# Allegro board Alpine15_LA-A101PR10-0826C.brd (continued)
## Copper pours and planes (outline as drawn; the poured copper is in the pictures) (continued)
U2_LGATE2 on IN1 (solid shape): 57.02,33.47 57.02,31.69 56.9,31.57 56.26,31.57 56.2,31.63 56.2,32.58 56.07,32.71 56.07,33.54 56.13,33.6 56.9,33.6
U2_LGATE2 on IN3 (solid shape): 53.02,40.72 53.02,39.5 52.79,39.28 46.9,39.28 46.67,39.5 46.67,40.6 46.95,40.88 52.87,40.88
U2_PHASE1 on BOTTOM (solid shape): 60.39,34 60.39,32.93 59.07,31.61 58.59,31.61 58.51,31.68 58.51,32.55 59.3,33.34 59.3,34.05 59.33,34.07 60.32,34.07
U2_PHASE1 on BOTTOM (solid shape): 71.41,50.55 74.61,50.55 74.86,50.3 74.86,46.36 75.05,46.17 76.45,46.17 76.64,45.98 76.64,44.97 76.52,44.84 74.74,44.84 74.36,44.46 74.36,41.66 73.85,41.16 64.32,41.16 64.2,41.28 64.2,46.3 64.58,46.68 65.91,46.68 66.23,47 66.23,50.17 66.7,50.65 71.32,50.65
U2_PHASE1 on IN1 (solid shape): 61.34,32.9 61.34,32.01 60.96,31.63 59.06,31.63 58.8,31.88 58.8,32.65 59.18,33.03 61.21,33.03
U2_PHASE1 on IN1 (solid shape): 71.37,43.22 71.37,42.2 71.18,42.01 68.96,42.01 68.71,42.27 68.71,42.71 69.34,43.35 71.25,43.35
U2_PHASE2 on BOTTOM (solid shape): 55.56,33.98 55.56,33.03 55.94,32.65 55.94,31.63 55.82,31.5 55.31,31.5 55.12,31.69 55.12,32.27 54.55,32.84 54.55,33.98 54.61,34.04 55.5,34.04
U2_PHASE2 on BOTTOM (solid shape): 56.71,50.68 59.87,50.68 60.15,50.4 60.15,47.02 59.88,46.74 58.1,46.74 57.66,46.3 57.66,41.47 57.47,41.28 47.43,41.28 47.05,41.66 47.05,43.7 46.74,44.01 45.21,44.01 45.09,44.14 45.09,45.16 45.21,45.28 46.8,45.28 47.05,45.54 47.05,47.76 49.97,50.68 49.99,50.68 50.05,50.74 56.65,50.74
U2_PHASE2 on IN1 (solid shape): 49.59,42.93 49.59,41.66 49.4,41.47 47.37,41.47 47.05,41.79 47.05,42.93 47.24,43.12 49.4,43.12
U2_PHASE2 on IN1 (solid shape): 55.88,32.52 55.88,31.63 55.75,31.5 54.74,31.5 53.85,32.39 53.85,32.58 53.98,32.71 55.69,32.71
U2_UGATE1 on BOTTOM (solid shape): 74.67,51.58 74.67,50.99 74.49,50.81 72.01,50.81 72,50.81 71.83,50.81 71.73,50.91 71.73,51.65 71.85,51.76 74.49,51.76
U2_UGATE1 on IN1 (solid shape): 61.91,30.81 61.91,29.6 61.85,29.54 60.13,29.54 59.88,29.79 59.88,30.81 60.07,31 61.72,31
U2_UGATE1 on IN1 (solid shape): 73.22,50.68 73.22,49.66 73.03,49.47 72.2,49.47 71.69,49.98 71.69,51.63 71.76,51.7 72.2,51.7
U2_UGATE2 on BOTTOM (solid shape): 54.26,31.63 54.26,30.36 54.13,30.23 53.91,30.23 53.53,30.61 53.53,31.63 53.59,31.69 54.2,31.69
U2_UGATE2 on BOTTOM (solid shape): 60.13,51.83 60.13,51.14 59.96,50.97 57.71,50.97 57.55,51.13 57.55,51.73 57.86,52.04 59.92,52.04
U2_UGATE2 on IN1 (solid shape): 54.29,31.19 54.29,30.42 54.1,30.23 52.77,30.23 52.13,30.87 52.13,31.63 52.26,31.76 53.72,31.76
U2_UGATE2 on IN1 (solid shape): 59.03,51.22 59.03,50.05 58.73,49.76 57.08,49.76 56.8,50.03 56.55,50.03 56.45,50.13 56.45,50.69 56.8,51.04 56.81,51.04 57.28,51.51 58.74,51.51
UG_3V on TOP (solid shape): 227.14,155.58 227.14,154.76 227.01,154.63 226.12,154.63 225.99,154.76 225.99,155.58 226.12,155.71 227.01,155.71
UG_3V on TOP (solid shape): 214.87,155.15 214.87,153.29 214.8,153.21 214.47,153.21 214.39,153.29 214.39,154.27 214.29,154.37 214,154.37 213.96,154.41 213.96,155.24 214.01,155.29 214.73,155.29
UG_3V on IN2 (solid shape): 227.35,155.56 227.35,154.51 227.01,154.18 226.19,154.18 225.81,154.56 225.81,155.58 226,155.77 227.14,155.77
UG_3V on IN2 (solid shape): 215.09,154.05 216.57,154.05 216.83,153.78 216.83,153.48 216.37,153.02 216.37,153.02 216.02,152.68 214.79,152.68 214.41,153.05 214.41,154.15 214.54,154.27 214.86,154.27
UG_5V on TOP (solid shape): 227.14,159.14 227.14,158.25 227.01,158.12 226.12,158.12 225.99,158.25 225.99,159.14 226.12,159.27 227.01,159.27
UG_5V on TOP (solid shape): 214.94,159.07 214.94,158.19 214.63,157.89 214.33,157.89 214.24,157.8 214.24,157.52 214.21,157.49 214,157.49 213.95,157.54 213.95,158.41 214.06,158.52 214.23,158.52 214.32,158.61 214.32,159.02 214.39,159.09 214.91,159.09
UG_5V on IN2 (solid shape): 227.34,159.19 227.34,158.43 227.21,158.3 225.18,158.3 224.8,158.68 224.8,159.13 224.99,159.32 227.21,159.32
UG_5V on IN2 (solid shape): 216.37,160.06 216.37,158.67 215.87,158.17 214.8,158.17 214.67,158.05 214.16,158.05 214.03,158.17 214.03,159.13 214.22,159.32 214.6,159.32 215.67,160.39 216.04,160.39
UG_+VDDRP on BOTTOM (solid shape): 43.27,42.84 43.27,40.52 43.17,40.42 42.37,40.42 42.18,40.61 42.18,42.84 42.31,42.96 43.15,42.96
UG_+VDDRP on IN2 (solid shape): 37.45,33.05 37.45,32.04 37.39,31.97 35.42,31.97 35.23,32.17 35.23,32.93 35.42,33.12 37.39,33.12
UG_+VDDRP on IN2 (solid shape): 43.33,42.76 43.33,39.28 43.01,38.96 42.31,38.96 42.18,39.09 42.18,42.84 42.26,42.91 43.17,42.91
N07808 on TOP (solid shape): 158.89,170.85 158.89,169.53 158.49,169.12 156.28,169.12 156.05,169.35 156.05,170.85 156.23,171.03 158.72,171.03
N07808 on BOTTOM (solid shape): 158.84,170.88 158.84,170.39 158.69,170.24 155.82,170.24 155.72,170.34 155.72,170.8 155.87,170.95 158.77,170.95
N07946 on BOTTOM (solid shape): 146.02,172.35 146.02,172.12 146.32,171.82 147.18,171.82 147.4,171.6 147.4,166.62 147.34,166.56 145.96,166.56 145.89,166.64 145.89,168.21 145.53,168.57 142.99,168.57 142.79,168.77 142.79,172.22 143.09,172.53 145.84,172.53
N07954 on BOTTOM (solid shape): 145.56,168.31 145.56,166.97 145.69,166.84 145.69,166.51 145.86,166.33 147.44,166.33 147.49,166.28 147.49,165.54 147.44,165.49 145,165.49 144.9,165.59 144.9,166.36 144.59,166.66 143.91,166.66 143.78,166.79 143.78,168.31 143.91,168.44 145.43,168.44
N18768391 on TOP (solid shape): 234.05,37.68 234.05,35.52 233.92,35.39 233.09,35.39 232.88,35.6 232.88,36.5 232.86,36.5 232.86,36.52 232.35,36.52 232.35,36.7 232.86,36.7 232.86,36.73 232.88,36.73 232.88,37.24 232.88,37.71 232.96,37.78 233.95,37.78
N18768391 on BOTTOM (solid shape): 233.94,38.42 234.08,38.39 234.22,38.42 237.68,38.42 237.68,37.71 235.93,37.71 235.86,37.63 235.86,37.43 235.93,37.35 237.73,37.35 237.73,36.69 234,36.69 233.8,36.49 233.8,35.57 233.65,35.42 232.55,35.42 232.45,35.52 232.45,37.92 232.94,38.42
N19821558 on BOTTOM (solid shape): 37.89,33.64 37.89,31.68 37.84,31.63 36.98,31.63 36.95,31.66 36.95,33.66 37,33.71 37.82,33.71
N19821679 on BOTTOM (solid shape): 35.4,39.33 35.4,37.47 35.3,37.37 33.5,37.37 33.16,37.71 33.16,39.43 33.31,39.58 33.65,39.58 35.15,39.58
N19847781 on TOP (solid shape): 214.88,162 214.88,161.23 214.76,161.11 212.72,161.11 212.6,161.23 212.6,162 212.79,162.19 214.69,162.19
N19847834 on TOP (solid shape): 214.83,151.52 214.83,150.91 214.7,150.78 212.47,150.78 212.39,150.86 212.39,151.49 212.52,151.62 214.73,151.62
N19847903 on TOP (solid shape): 223.9,164.22 223.9,163.27 223.77,163.14 221.11,163.14 220.92,163.33 220.92,164.22 221.04,164.35 223.77,164.35
N19847904 on TOP (solid shape): 227.1,147.85 227.1,145.99 226.98,145.87 225.64,145.87 225.06,146.45 225.06,148.04 225.11,148.09 226.86,148.09
N19848836 on BOTTOM (solid shape): 44.06,15.58 43.48,15.58 43.48,17.49 44.06,17.49
N19850625 on TOP (solid shape): 114.61,161.67 114.61,161.23 114.99,160.84 116.96,160.84 117.02,160.78 117.02,160.65 116.96,160.59 113.34,160.59 113.15,160.78 113.15,161.67 113.34,161.86 114.42,161.86
N19850625 on BOTTOM (solid shape): 121.68,181.27 121.68,177.15 119.45,174.92 119.04,174.92 116.86,172.73 116.86,169.75 116.22,169.11 112.55,169.11 112.36,169.3 112.36,173.01 112.79,173.44 112.79,175.04 111.97,175.86 109.43,175.86 109.16,176.14 109.16,180.81 110,181.65 121.3,181.65
N19850625 on IN2 (solid shape): 113.83,161.61 113.83,160.62 113.78,160.57 112.61,160.57 112.36,160.82 112.36,162.11 113.33,162.11
N19850625 on IN2 (solid shape): 114.77,171.56 114.77,170.37 114.67,170.27 113.91,170.27 113.83,170.34 112.89,170.34 112.89,171.41 113.15,171.66 114.67,171.66
N19850655 on BOTTOM (solid shape): 112.39,174.79 112.39,173.62 111.85,173.09 110.1,173.09 109.97,173.21 109.97,174.79 110.07,174.89 112.28,174.89
N22916336 on TOP (solid shape): 63.71,106.06 65.83,106.06 65.9,105.99 65.9,105.73 66.05,105.58 66.08,105.55 66.08,104.44 65.97,104.33 63.92,104.33 63.85,104.4 63.28,104.4 63.24,104.43 63.24,104.45 62.89,104.75 62.54,104.44 62.53,104.4 61.56,104.4 61.52,104.44 61.52,104.46 61.41,104.7 61.17,104.8 61.15,104.8 61.03,104.93 61.03,106.5 61.07,106.55 63.23,106.55
N22916336 on BOTTOM (solid shape): 64.18,106.26 64.35,106.21 64.52,106.26 65.02,106.26 65.18,106.21 65.35,106.25 65.36,106.26 65.45,106.26 65.55,106.16 65.55,105.48 64.66,104.59 63.6,104.59 63.6,104.59 63.14,104.59 62.89,104.72 62.63,104.59 62.32,104.59 61.6,105.31 61.6,106.14 61.68,106.22 61.79,106.22 61.87,106.21 61.94,106.22 62.64,106.22 62.67,106.21 62.74,106.2 63.52,106.2 63.64,106.22 63.72,106.26
N23032286 on TOP (solid shape): 69.4,102.65 69.41,102.61 69.43,102.57 69.45,102.52 69.49,102.49 69.52,102.45 69.57,102.43 69.61,102.41 69.65,102.4 69.73,102.31 69.99,102.05 69.99,101.26 70.37,100.88 70.5,100.88 70.58,100.8 70.58,100.1 70.25,99.77 67.91,99.77 67.82,99.86 67.05,99.86 66.92,99.73 65.68,99.73 65.55,99.86 65.55,100.89 66.42,101.75 67.09,101.75 67.26,101.93 67.83,101.93 67.83,101.88 67.84,101.83 67.85,101.78 67.88,101.74 67.91,101.7 67.94,101.66 67.98,101.63 68.03,101.61 68.07,101.59 68.12,101.59 68.17,101.59 68.22,101.59 68.27,101.61 68.32,101.63 68.36,101.66 68.39,101.7 68.42,101.74 68.44,101.78 68.46,101.83 68.47,101.88 68.47,101.93 68.46,101.98 68.44,102.03 68.42,102.07 68.39,102.11 68.36,102.15 68.32,102.18 68.27,102.2 68.22,102.21 68.17,102.22 68.12,102.22 68.07,102.21 68.03,102.2 67.98,102.18 67.94,102.15 67.91,102.11 67.88,102.07 67.85,102.03 67.84,101.98 67.83,101.93 67.26,101.93 68.22,102.88 69.16,102.88
N23621118 on BOTTOM (solid shape): 46.86,42.49 46.86,41.22 46.1,40.46 45.15,40.46 45.02,40.58 45.02,42.43 45.21,42.62 46.74,42.62
N23709542 on BOTTOM (solid shape): 76.71,43.25 76.71,41.64 76.16,41.09 75.06,41.09 74.93,41.22 74.93,43.31 74.99,43.38 76.58,43.38
N35502990 on BOTTOM (solid shape): 225.87,105.5 225.87,104.18 225.42,103.72 224.68,103.72 224.55,103.85 224.55,105.96 224.68,106.08 225.29,106.08

Small or netless copper shapes (teardrops, artwork), in the pictures only: 51 on TOP, 553 on BOTTOM, 1 on IN1, 21 on IN2

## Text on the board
Ref Des/Silkscreen Bottom: DDR3L | LOW VOLTAGE | DIMM  A | DIMM  B | H36 | H26 | H27
User.Comments: LA-A101P | 2014-08-26 | 2013-08-26 | VAW50 | Win
Ref Des/Silkscreen Top: H23 | H25 | H24 | H37 | B | H19 | H18 | A
BODY_CENTER: +1.5V_GPU | +GPU_CORE | +1.05V_M | GND | +PWR_SRC | +VCC_CORE | +1.35V_MEM | +3.3V_RUN | +5V_RUN | +1.05V_RUN | +DOCK_PWR_BAR | +1.5V_RUN | +3.3V_ALW_PCH | +3.3V_ALW | +5V_ALW | +3.3V_WLAN | GNDA
USER_PART_NUM_BOTTOM: 20,02 | 177,75 | 164,09 | 157,45 | 131,27 | 119,6 | 107,63 | 103,35 | 96,32 | 97,59 | 98,34 | 98,85 | 106,7 | 129,59 | 202,46 | 202,84 | 214,57 | 215,75 | 313,95 | 30,36 | 82,1 | 101,64 | 166,22 | 19,8
USER_PART_NUM_TOP: 15,3 | 5,32 | {\Fgdt;n}\Ftxt;6 | 0 | 11 | {\Fgdt;n}\Ftxt;8 | {\Fgdt;n}\Ftxt;3 | {\Fgdt;n}\Ftxt;1,2 | {\Fgdt;n}\Ftxt;6,4 | {\Fgdt;n}\Ftxt;4,4 | {\Fgdt;n}\Ftxt;2,5 | {\Fgdt;n}\Ftxt;0,65 | {\Fgdt;n}\Ftxt;3,3 | {\Fgdt;n}\Ftxt;4,6 | {\Fgdt;n}\Ftxt;6,6 | {\Fgdt;n}\Ftxt;7,9 | 7,5 | 1,5 | 174,95 | 162,1 | 161,1 | 132,1 | 122,33 | 114,88 | 114,82 | 82,22 | 71,36 | 68,1 | 66,1 | 62,22 | 58,51 | 29,4 | 41,1 | 79,01 | 82,43 | 89,18 | 101,18 | 109,87 | 76,28 | 84,9 | 140,91 | 175,87 | 105,9 | 185,33 | 187,4 | 211,92 | 217,27 | 228,9 | 231,1 | 231,38 | 285,55 | 325,01 | 333,1 | 341,1 | 62,5 | 59,18 | 64,27 | 94,35 | 97,93 | 105,6 | 140,38 | 143,95 | 146,1 | 157,11 | 162,2 | 183,6 | 1 | {\Fgdt;n}\Ftxt;1,6 | {\Fgdt;n}\Ftxt;1,1 | {\Fgdt;n}\Ftxt;2,3
DEVICE_TYPE_TOP: 14,15 | 8 | 10 | 8,35 | 101,75 | 7,2 | 8,2 | 17,11 | 9,2 | 172,9 | 162,09 | 158,42 | 136,65 | 120,42 | 112,98 | 106,54 | 89,9 | 87,14 | 80,83 | 68,54 | 59,58 | 34,69 | 49,73 | 69,13 | 82,44 | 85,6 | 86,29 | 129,36 | 166,68 | 212,71 | 214,84 | 222,42 | 22,43 | 231,43 | 316,3 | 15 | 57,27 | 79 | 171,12 | 8,9 | 7,87 | 12,2 | 10,2
COMPVAL_TYPE_TOP: 9,15 | 11,39 | 13,52 | 29,25 | 19,48 | 182,3 | 150,9 | 95,25 | 81,1 | 42,1 | 23,43 | 87,18 | 93,05 | 107,1 | 161,68 | 166,15 | 205,34 | 218,63 | 230,62 | 233,3 | 236,75 | 258,19 | 301,1 | 334,88 | 33,04 | 72,47 | 102,26 | 124,1 | 138,3 | 173,6 | 175,01 | 183,5 | 185,2
PAGE_OUTLINE: {\Fgdt;n}\Ftxt;2,5 | R4 | {\Fgdt;n}\Ftxt;8 | 1 | {\Fgdt;n}\Ftxt;6,6 | 1,5 | {\Fgdt;n}\Ftxt;4,4 | {\Fgdt;n}\Ftxt;5,2 | {\Fgdt;n}\Ftxt;6
User.9: 19,6 | 82,51 | 24,01 | 86,62 | 103,7 | 125,62 | 161,43 | 27 | 63,81 | 109,61 | 63,5 | 78,7
User.10: 10,5 | 6,5 | 4,5 | 4,07 | 11,14 | 8,15 | 6,33 | 1,05 | 12,23 | 296,03 | 184,9 | 165,35 | 149,49 | 123,34 | 119,37 | 107,5 | 92 | 86,78 | 84,35 | 70,85 | 68,11 | 64,61 | 79,5 | 81 | 85,5 | 136,94 | 151,94 | 184,4 | 190,4 | 228,67 | 232,05 | 235,1 | 236,6 | 238,75 | 290,03 | 344,1 | 42,3 | 43,3 | 110,58 | 118,58 | 139,4 | 182,01 | 184,51 | 183,1 | 187,9 | 14 | 3,1 | 0,8 | 3 | 7,5 | 14,9
User.11: 20,02 | 177,75 | 164,09 | 157,45 | 131,27 | 119,6 | 107,63 | 103,35 | 96,32 | 97,59 | 98,34 | 98,85 | 106,7 | 129,59 | 202,46 | 202,84 | 214,57 | 215,75 | 313,95 | 30,36 | 82,1 | 101,64 | 166,22 | 19,8
User.15: 19,48 | 9,15 | 11,39 | 13,52 | 29,25 | 182,3 | 150,9 | 95,25 | 81,1 | 42,1 | 23,43 | 87,18 | 93,05 | 107,1 | 161,68 | 166,15 | 205,34 | 218,63 | 230,62 | 233,3 | 236,75 | 258,19 | 301,1 | 334,88 | 33,04 | 72,47 | 102,26 | 124,1 | 138,3 | 173,6 | 175,01 | 183,5 | 185,2
User.38: L1-TOP | L2-GND1 | L3-IN1 | L4-VCC | L5-IN2 | L6-IN3 | L7-GND2 | L8-BOT | LAYER | NAME | trace Width | 40 ohm | 45 ohm | 50 ohm | Width/space | 80 ohm | 83 ohm | 85 ohm | 90 ohm | 100 ohm | ref | STACKUP: 8 LAYER | 6mil | 5.5mil | 4.8mil | 4.5mil | THICKNESS=1.2mm | 3.8mil | 4mil | 3.8 / 3.2 | 4 / 3.5 | 4 / 3.4 | 3.8/3.8 | 4 / 4 | 4 / 4.2 | 4 / 4.5 | 3.8 / 4.5 | 3.4 / 3.5 | 4 / 6.5 | 3.8 / 6.5 | 3.4 / 4.8 | 3.5 / 9.5 | 3.5 / 12 | 3.6mil | L5/L7 | SB_1_2mm-6L and 8L and 10L(4mil 50ohm)_130102
User.39: FIGURE | SIZE | 7.0 | 8.0 | 10.0 | 22.0 | 28.0 | 39.0 | 47.0 | 91.0 | 118.0 | 130.0 | 150.0 | 173.0 | 26.0 | 31.0 | 35.0 | 40.0 | 43.0 | 63.0 | 98.0 | 39.0x33.0 | 45.0x37.0 | 63.0x35.0 | 69.0x20.0 | 71.0x31.0 | 75.0x37.0 | 102.0x31.0 | 112.0x39.0 | 114.0x39.0 | 118.0x33.0 | 138.0x98.0 | 157.0x98.0 | 75.0x47.0 | DRILL CHART: TOP to BOTTOM | ALL UNITS ARE IN MILS | PLATED | NON-PLATED | QTY | 316 | 5096 | 2129 | 19 | 9 | 13 | 5 | 2 | 4 | 1
